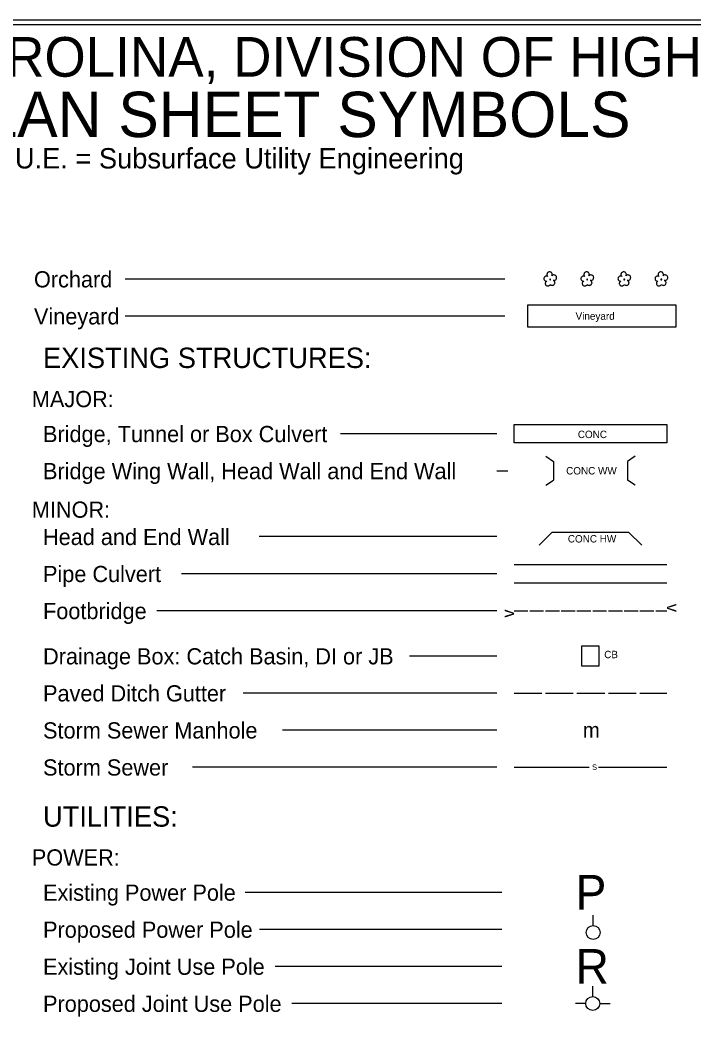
# Model space of a CAD drawing. Extents: x 2241278 to 2254132, y 649924 to 670434.
# Drawn here: x 2249172 to 2250991, y 658059 to 660787 of the extents above; entities that cross this region are included whole.
import ezdxf

# ---------------------------------------------------------------- set-up
doc = ezdxf.new("R2010")
doc.units = 0
doc.layers.add('Sheet Plot Border Inside CELL', color=7, linetype='Continuous')
doc.layers.add('Sheet Symbology CELL', color=7, linetype='Continuous')

msp = doc.modelspace()

# ---------------------------------------------------------------- linework, layer by layer
at = {"layer": 'Sheet Plot Border Inside CELL'}
msp.add_lwpolyline([(2244623.8, 655511.4), (2252956.3, 655511.4), (2252956.3, 660786.9), (2244623.8, 660786.9)], close=True, dxfattribs=at)
at = {"layer": 'Sheet Symbology CELL'}
for p, q in [((2250480.4, 660088.3), (2249455.7, 660088.3)), ((2250480.4, 659988.3), (2249455.7, 659988.3)), ((2250458.8, 659670.8), (2250036.7, 659670.8)), ((2250591.1, 659610.1), (2250611.6, 659595.8)), ((2250611.6, 659595.8), (2250611.6, 659545.8)), ((2250832.1, 659610.1), (2250811.6, 659595.8)), ((2250811.6, 659595.8), (2250811.6, 659545.8)), ((2250458.8, 659570.8), (2250488.8, 659570.8)), ((2250591.1, 659531.5), (2250611.6, 659545.8)), ((2250832.1, 659531.5), (2250811.6, 659545.8)), ((2250573.1, 659370.1), (2250608.5, 659405.5)), ((2250608.5, 659405.5), (2250814.7, 659405.5)), ((2250814.7, 659405.5), (2250850.1, 659370.1)), ((2250458.8, 659393), (2249817.3, 659393)), ((2250458.8, 659293), (2249607.9, 659293)), ((2250505.3, 659318), (2250917.8, 659318)), ((2250505.3, 659268), (2250917.8, 659268)), ((2250458.8, 659193), (2249541.5, 659193)), ((2250505.3, 659193), (2250542.8, 659193)), ((2250547.8, 659193), (2250585.3, 659193)), ((2250590.3, 659193), (2250627.8, 659193)), ((2250632.8, 659193), (2250670.3, 659193)), ((2250675.3, 659193), (2250712.8, 659193)), ((2250717.8, 659193), (2250755.3, 659193)), ((2250760.3, 659193), (2250797.8, 659193)), ((2250802.8, 659193), (2250840.3, 659193)), ((2250845.3, 659193), (2250882.8, 659193)), ((2250887.8, 659193), (2250917.8, 659193)), ((2250458.8, 659070.8), (2250222.8, 659070.8)), ((2250458.8, 658970.8), (2249774.1, 658970.8)), ((2250505.3, 658970.8), (2250580.3, 658970.8)), ((2250590.3, 658970.8), (2250665.3, 658970.8)), ((2250675.3, 658970.8), (2250750.3, 658970.8)), ((2250760.3, 658970.8), (2250835.3, 658970.8)), ((2250845.3, 658970.8), (2250917.8, 658970.8)), ((2250458.8, 658870.8), (2249880.5, 658870.8)), ((2250458.8, 658770.8), (2249637.8, 658770.8)), ((2250505.3, 658770.8), (2250708, 658770.8)), ((2250733, 658770.8), (2250917.8, 658770.8)), ((2250472.8, 658432.9), (2249779.3, 658432.9)), ((2250718.9, 658343.4), (2250718.9, 658371.6)), ((2250472.8, 658332.9), (2249818.2, 658332.9)), ((2250472.8, 658232.9), (2249860.2, 658232.9)), ((2250717.8, 658151.7), (2250717.8, 658179.8)), ((2250472.8, 658132.9), (2249905.2, 658132.9)), ((2250699.1, 658132.9), (2250671, 658132.9)), ((2250736.6, 658132.9), (2250764.7, 658132.9))]:
    msp.add_line(p, q, dxfattribs=at)
for points in [[(2252893.8, 660774.2), (2245393.8, 660774.2), (2245393.8, 655529.3), (2252893.8, 655529.3)], [(2250687.5, 659044.3), (2250735.6, 659044.3), (2250735.6, 659097.4), (2250687.5, 659097.4)]]:
    msp.add_lwpolyline(points, close=True, dxfattribs=at)
for points in [[(2250607.6, 660097.1), (2250608.4, 660098.6), (2250608.6, 660100.1), (2250608.4, 660101.6), (2250608.1, 660103.1), (2250607.4, 660104.3), (2250606.6, 660105.6), (2250605.4, 660106.6), (2250604.1, 660107.3), (2250602.4, 660107.8), (2250601.1, 660107.8), (2250599.6, 660107.6), (2250598.1, 660107.1), (2250596.9, 660106.3), (2250595.6, 660105.3), (2250594.9, 660103.8), (2250594.4, 660102.6), (2250594.1, 660101.1), (2250594.1, 660099.6), (2250594.4, 660098.1), (2250595.1, 660096.8), (2250596.1, 660095.3), (2250594.9, 660096.1), (2250593.4, 660096.3), (2250591.9, 660096.3), (2250590.6, 660095.8), (2250589.4, 660095.3), (2250588.1, 660094.3), (2250587.1, 660093.3), (2250586.4, 660092.1), (2250586.1, 660090.8), (2250585.9, 660089.1), (2250586.1, 660087.8), (2250586.6, 660086.6), (2250587.6, 660085.3), (2250588.4, 660084.3), (2250589.6, 660083.6), (2250591.1, 660082.8), (2250592.4, 660082.6), (2250593.9, 660082.6), (2250592.6, 660082.1), (2250591.4, 660081.1), (2250590.6, 660080.1), (2250590.1, 660078.6), (2250589.6, 660077.1), (2250589.6, 660075.8), (2250589.9, 660074.3), (2250590.6, 660073.1), (2250591.4, 660071.8), (2250592.4, 660070.8), (2250593.6, 660070.1), (2250594.9, 660069.6), (2250596.4, 660069.6), (2250597.9, 660069.6), (2250599.1, 660069.8), (2250600.4, 660070.8), (2250601.6, 660071.6), (2250602.9, 660073.8)], [(2250603.4, 660088.3), (2250602.6, 660088.3), (2250602.1, 660088.1), (2250601.6, 660087.8), (2250601.6, 660087.1), (2250601.6, 660086.6), (2250602.1, 660086.1), (2250602.9, 660086.1), (2250603.4, 660086.1), (2250603.9, 660086.6), (2250604.1, 660087.3), (2250603.9, 660087.8), (2250603.4, 660088.3)], [(2250602.9, 660073.8), (2250605.9, 660072.1), (2250607.4, 660071.6), (2250608.9, 660071.3), (2250610.4, 660071.6), (2250611.6, 660072.1), (2250612.9, 660072.8), (2250614.1, 660073.8), (2250614.9, 660075.1), (2250615.4, 660076.3), (2250615.9, 660077.8), (2250615.6, 660079.3), (2250615.4, 660080.8), (2250614.4, 660082.3), (2250613.6, 660083.3), (2250612.4, 660084.1), (2250610.9, 660084.8), (2250612.4, 660084.6), (2250614.1, 660084.6), (2250615.4, 660085.1), (2250616.9, 660085.8), (2250618.1, 660086.6), (2250619.1, 660087.8), (2250619.9, 660089.3), (2250620.1, 660090.8), (2250620.4, 660092.3), (2250620.1, 660093.8), (2250619.6, 660095.3), (2250618.6, 660096.6), (2250617.4, 660097.8), (2250616.1, 660098.6), (2250614.6, 660099.1), (2250613.1, 660099.3), (2250611.6, 660099.3), (2250610.1, 660098.8), (2250608.9, 660098.1), (2250607.6, 660097.1)], [(2250707.6, 660097.1), (2250708.4, 660098.6), (2250708.6, 660100.1), (2250708.4, 660101.6), (2250708.1, 660103.1), (2250707.4, 660104.3), (2250706.6, 660105.6), (2250705.4, 660106.6), (2250704.1, 660107.3), (2250702.4, 660107.8), (2250701.1, 660107.8), (2250699.6, 660107.6), (2250698.1, 660107.1), (2250696.9, 660106.3), (2250695.6, 660105.3), (2250694.9, 660103.8), (2250694.4, 660102.6), (2250694.1, 660101.1), (2250694.1, 660099.6), (2250694.4, 660098.1), (2250695.1, 660096.8), (2250696.1, 660095.3), (2250694.9, 660096.1), (2250693.4, 660096.3), (2250691.9, 660096.3), (2250690.6, 660095.8), (2250689.4, 660095.3), (2250688.1, 660094.3), (2250687.1, 660093.3), (2250686.4, 660092.1), (2250686.1, 660090.8), (2250685.9, 660089.1), (2250686.1, 660087.8), (2250686.6, 660086.6), (2250687.6, 660085.3), (2250688.4, 660084.3), (2250689.6, 660083.6), (2250691.1, 660082.8), (2250692.4, 660082.6), (2250693.9, 660082.6), (2250692.6, 660082.1), (2250691.4, 660081.1), (2250690.6, 660080.1), (2250690.1, 660078.6), (2250689.6, 660077.1), (2250689.6, 660075.8), (2250689.9, 660074.3), (2250690.6, 660073.1), (2250691.4, 660071.8), (2250692.4, 660070.8), (2250693.6, 660070.1), (2250694.9, 660069.6), (2250696.4, 660069.6), (2250697.9, 660069.6), (2250699.1, 660069.8), (2250700.4, 660070.8), (2250701.6, 660071.6), (2250702.9, 660073.8)], [(2250703.4, 660088.3), (2250702.6, 660088.3), (2250702.1, 660088.1), (2250701.6, 660087.8), (2250701.6, 660087.1), (2250701.6, 660086.6), (2250702.1, 660086.1), (2250702.9, 660086.1), (2250703.4, 660086.1), (2250703.9, 660086.6), (2250704.1, 660087.3), (2250703.9, 660087.8), (2250703.4, 660088.3)], [(2250702.9, 660073.8), (2250705.9, 660072.1), (2250707.4, 660071.6), (2250708.9, 660071.3), (2250710.4, 660071.6), (2250711.6, 660072.1), (2250712.9, 660072.8), (2250714.1, 660073.8), (2250714.9, 660075.1), (2250715.4, 660076.3), (2250715.9, 660077.8), (2250715.6, 660079.3), (2250715.4, 660080.8), (2250714.4, 660082.3), (2250713.6, 660083.3), (2250712.4, 660084.1), (2250710.9, 660084.8), (2250712.4, 660084.6), (2250714.1, 660084.6), (2250715.4, 660085.1), (2250716.9, 660085.8), (2250718.1, 660086.6), (2250719.1, 660087.8), (2250719.9, 660089.3), (2250720.1, 660090.8), (2250720.4, 660092.3), (2250720.1, 660093.8), (2250719.6, 660095.3), (2250718.6, 660096.6), (2250717.4, 660097.8), (2250716.1, 660098.6), (2250714.6, 660099.1), (2250713.1, 660099.3), (2250711.6, 660099.3), (2250710.1, 660098.8), (2250708.9, 660098.1), (2250707.6, 660097.1)], [(2250807.6, 660097.1), (2250808.4, 660098.6), (2250808.6, 660100.1), (2250808.4, 660101.6), (2250808.1, 660103.1), (2250807.4, 660104.3), (2250806.6, 660105.6), (2250805.4, 660106.6), (2250804.1, 660107.3), (2250802.4, 660107.8), (2250801.1, 660107.8), (2250799.6, 660107.6), (2250798.1, 660107.1), (2250796.9, 660106.3), (2250795.6, 660105.3), (2250794.9, 660103.8), (2250794.4, 660102.6), (2250794.1, 660101.1), (2250794.1, 660099.6), (2250794.4, 660098.1), (2250795.1, 660096.8), (2250796.1, 660095.3), (2250794.9, 660096.1), (2250793.4, 660096.3), (2250791.9, 660096.3), (2250790.6, 660095.8), (2250789.4, 660095.3), (2250788.1, 660094.3), (2250787.1, 660093.3), (2250786.4, 660092.1), (2250786.1, 660090.8), (2250785.9, 660089.1), (2250786.1, 660087.8), (2250786.6, 660086.6), (2250787.6, 660085.3), (2250788.4, 660084.3), (2250789.6, 660083.6), (2250791.1, 660082.8), (2250792.4, 660082.6), (2250793.9, 660082.6), (2250792.6, 660082.1), (2250791.4, 660081.1), (2250790.6, 660080.1), (2250790.1, 660078.6), (2250789.6, 660077.1), (2250789.6, 660075.8), (2250789.9, 660074.3), (2250790.6, 660073.1), (2250791.4, 660071.8), (2250792.4, 660070.8), (2250793.6, 660070.1), (2250794.9, 660069.6), (2250796.4, 660069.6), (2250797.9, 660069.6), (2250799.1, 660069.8), (2250800.4, 660070.8), (2250801.6, 660071.6), (2250802.9, 660073.8)], [(2250803.4, 660088.3), (2250802.6, 660088.3), (2250802.1, 660088.1), (2250801.6, 660087.8), (2250801.6, 660087.1), (2250801.6, 660086.6), (2250802.1, 660086.1), (2250802.9, 660086.1), (2250803.4, 660086.1), (2250803.9, 660086.6), (2250804.1, 660087.3), (2250803.9, 660087.8), (2250803.4, 660088.3)], [(2250802.9, 660073.8), (2250805.9, 660072.1), (2250807.4, 660071.6), (2250808.9, 660071.3), (2250810.4, 660071.6), (2250811.6, 660072.1), (2250812.9, 660072.8), (2250814.1, 660073.8), (2250814.9, 660075.1), (2250815.4, 660076.3), (2250815.9, 660077.8), (2250815.6, 660079.3), (2250815.4, 660080.8), (2250814.4, 660082.3), (2250813.6, 660083.3), (2250812.4, 660084.1), (2250810.9, 660084.8), (2250812.4, 660084.6), (2250814.1, 660084.6), (2250815.4, 660085.1), (2250816.9, 660085.8), (2250818.1, 660086.6), (2250819.1, 660087.8), (2250819.9, 660089.3), (2250820.1, 660090.8), (2250820.4, 660092.3), (2250820.1, 660093.8), (2250819.6, 660095.3), (2250818.6, 660096.6), (2250817.4, 660097.8), (2250816.1, 660098.6), (2250814.6, 660099.1), (2250813.1, 660099.3), (2250811.6, 660099.3), (2250810.1, 660098.8), (2250808.9, 660098.1), (2250807.6, 660097.1)], [(2250907.6, 660097.1), (2250908.4, 660098.6), (2250908.6, 660100.1), (2250908.4, 660101.6), (2250908.1, 660103.1), (2250907.4, 660104.3), (2250906.6, 660105.6), (2250905.4, 660106.6), (2250904.1, 660107.3), (2250902.4, 660107.8), (2250901.1, 660107.8), (2250899.6, 660107.6), (2250898.1, 660107.1), (2250896.9, 660106.3), (2250895.6, 660105.3), (2250894.9, 660103.8), (2250894.4, 660102.6), (2250894.1, 660101.1), (2250894.1, 660099.6), (2250894.4, 660098.1), (2250895.1, 660096.8), (2250896.1, 660095.3), (2250894.9, 660096.1), (2250893.4, 660096.3), (2250891.9, 660096.3), (2250890.6, 660095.8), (2250889.4, 660095.3), (2250888.1, 660094.3), (2250887.1, 660093.3), (2250886.4, 660092.1), (2250886.1, 660090.8), (2250885.9, 660089.1), (2250886.1, 660087.8), (2250886.6, 660086.6), (2250887.6, 660085.3), (2250888.4, 660084.3), (2250889.6, 660083.6), (2250891.1, 660082.8), (2250892.4, 660082.6), (2250893.9, 660082.6), (2250892.6, 660082.1), (2250891.4, 660081.1), (2250890.6, 660080.1), (2250890.1, 660078.6), (2250889.6, 660077.1), (2250889.6, 660075.8), (2250889.9, 660074.3), (2250890.6, 660073.1), (2250891.4, 660071.8), (2250892.4, 660070.8), (2250893.6, 660070.1), (2250894.9, 660069.6), (2250896.4, 660069.6), (2250897.9, 660069.6), (2250899.1, 660069.8), (2250900.4, 660070.8), (2250901.6, 660071.6), (2250902.9, 660073.8)], [(2250903.4, 660088.3), (2250902.6, 660088.3), (2250902.1, 660088.1), (2250901.6, 660087.8), (2250901.6, 660087.1), (2250901.6, 660086.6), (2250902.1, 660086.1), (2250902.9, 660086.1), (2250903.4, 660086.1), (2250903.9, 660086.6), (2250904.1, 660087.3), (2250903.9, 660087.8), (2250903.4, 660088.3)], [(2250902.9, 660073.8), (2250905.9, 660072.1), (2250907.4, 660071.6), (2250908.9, 660071.3), (2250910.4, 660071.6), (2250911.6, 660072.1), (2250912.9, 660072.8), (2250914.1, 660073.8), (2250914.9, 660075.1), (2250915.4, 660076.3), (2250915.9, 660077.8), (2250915.6, 660079.3), (2250915.4, 660080.8), (2250914.4, 660082.3), (2250913.6, 660083.3), (2250912.4, 660084.1), (2250910.9, 660084.8), (2250912.4, 660084.6), (2250914.1, 660084.6), (2250915.4, 660085.1), (2250916.9, 660085.8), (2250918.1, 660086.6), (2250919.1, 660087.8), (2250919.9, 660089.3), (2250920.1, 660090.8), (2250920.4, 660092.3), (2250920.1, 660093.8), (2250919.6, 660095.3), (2250918.6, 660096.6), (2250917.4, 660097.8), (2250916.1, 660098.6), (2250914.6, 660099.1), (2250913.1, 660099.3), (2250911.6, 660099.3), (2250910.1, 660098.8), (2250908.9, 660098.1), (2250907.6, 660097.1)], [(2250542.4, 660018.3), (2250942.4, 660018.3), (2250942.4, 659958.3), (2250542.4, 659958.3), (2250542.4, 660018.3)], [(2250505.3, 659695.8), (2250917.8, 659695.8), (2250917.8, 659645.8), (2250505.3, 659645.8), (2250505.3, 659695.8)]]:
    msp.add_lwpolyline(points, dxfattribs=at)
for centre in [(2250718.9, 658324.7), (2250717.8, 658132.9)]:
    msp.add_circle(centre, 18.8, dxfattribs=at)

# ---------------------------------------------------------------- texts
for s, height, p in [('STATE OF NORTH CAROLINA, DIVISION OF HIGHWAYS', 107.095, (2247646.6, 660634.4)), ('CONVENTIONAL  PLAN SHEET SYMBOLS', 122.402, (2247581.8, 660471.5)), ('Orchard', 43.75, (2249209.6, 660065.7)), ('Vineyard', 43.75, (2249209.6, 659965.7)), ('EXISTING STRUCTURES:', 55, (2249234, 659848.1)), ('MAJOR:', 43.75, (2249203.9, 659742.5)), ('Bridge, Tunnel or Box Culvert', 43.75, (2249234, 659648.1)), ('CONC', 20, (2250677.5, 659659)), ('Bridge Wing Wall, Head Wall and End Wall', 43.75, (2249234, 659548.1)), ('MINOR:', 43.75, (2249203.9, 659444)), ('Head and End Wall', 43.75, (2249234, 659370.2)), ('Pipe Culvert', 43.75, (2249234, 659270.3)), ('Footbridge', 43.75, (2249234.1, 659170.3)), ('Drainage Box: Catch Basin, DI or JB', 43.75, (2249234.1, 659048.1)), ('Paved Ditch Gutter', 43.75, (2249234.1, 658948.1)), ('Storm Sewer Manhole', 43.75, (2249234.1, 658848.1)), ('m', 41.2, (2250691, 658850.2)), ('Storm Sewer', 43.75, (2249234.1, 658748.1)), ('S', 15, (2250716, 658763.3)), ('UTILITIES:', 55, (2249234, 658610.1)), ('POWER:', 43.75, (2249203.9, 658505.2)), ('P', 93.8, (2250671, 658386)), ('Existing Power Pole', 43.75, (2249234.1, 658410.2)), ('Proposed Power Pole', 43.75, (2249234.1, 658310.2)), ('R', 93.8, (2250671, 658186)), ('Existing Joint Use Pole', 43.75, (2249234.1, 658210.3)), ('Proposed Joint Use Pole', 43.75, (2249234.1, 658110.2))]:
    msp.add_text(s, height=height, dxfattribs=at).set_placement(p)
for s, height, rotation, p in [('*S.U.E. = Subsurface Utility Engineering', 55, 360, (2249059.9, 660386.7)), ('Vineyard', 20, 0, (2250671.5, 659978.3)), ('CONC WW', 20, 0, (2250646, 659560.8)), ('CONC HW', 20, 360, (2250650.6, 659377.2)), ('v', 33, 270.2409, (2250917.8, 659211.7)), ('v', 33, 89.7591, (2250505.3, 659174.3)), ('CB', 20, 360, (2250748.8, 659064.9))]:
    msp.add_text(s, height=height, rotation=rotation, dxfattribs=at).set_placement(p)

doc.saveas('drawing.dxf')
